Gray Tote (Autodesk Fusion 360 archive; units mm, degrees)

design "Gray Tote" references "Air Volume Tank", "Pnuematic Hub", "Assorted terminals 3", "assorted terminals 2", "Neo 550 Motor", "assorted terminals 1", "Battery", "CIM Motor", "Robot Radio", "Power Distribution Hub", "NI roboRIO", "Spark Max Motor Controller", "Compressor VIAIR"
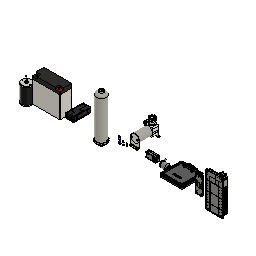
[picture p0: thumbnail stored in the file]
component_insert "Component Insert1"
component_insert "Component Insert4"
component_insert "Component Insert7"
component_insert "Component Insert8"
component_insert "Component Insert9"
component_insert "Component Insert10"
component_insert "Component Insert13"
component_insert "Component Insert15"
component_insert "Component Insert16"
component_insert "Component Insert17"
component_insert "Component Insert18"
component_insert "Component Insert19"
component_insert "Component Insert20"

design "Compressor VIAIR"
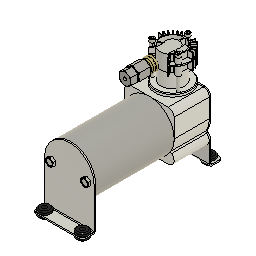
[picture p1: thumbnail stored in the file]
base_feature "Base Feature1"
base_feature "Base Feature1"
base_feature "Base Feature1"
base_feature "Base Feature1"
base_feature "Base Feature1"
base_feature "Base Feature1"
base_feature "Base Feature1"
base_feature "Base Feature1"
base_feature "Base Feature1"
base_feature "Base Feature1"
base_feature "Base Feature1"
as_built_joint "As-built1"
joint "Assemble1" alignAngle -180 alignOffsetX 0 alignOffsetY 0 alignOffsetZ 0
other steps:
create_component "CreateComponent1"
create_component "CreateComponent2"
create_component "CreateComponent3"
create_component "CreateComponent4"
create_component "CreateComponent5"
create_component "CreateComponent6"
create_component "CreateComponent7"
create_component "CreateComponent8"
create_component "CreateComponent9"
create_component "CreateComponent10"
create_component "CreateComponent11"
joint_origin "JointOrigin2"
joint_origin "JointOrigin2"

design "Battery"
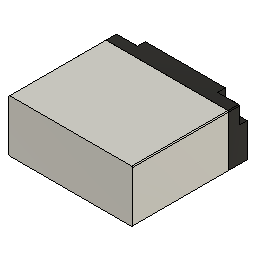
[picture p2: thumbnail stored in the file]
description: Robot Battery
part number: Robot Battery
base_feature "Base Feature"

design "CIM Motor"
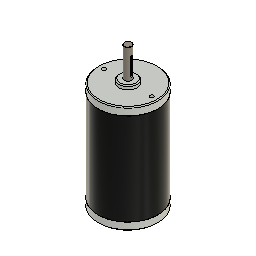
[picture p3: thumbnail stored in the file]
base_feature "Base Feature"

design "Robot Radio"
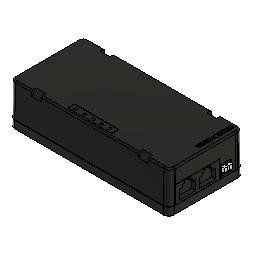
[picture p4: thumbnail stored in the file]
description: STEP AP214
part number: VH-109 Public 2024-01-02
base_feature "Base Feature"

design "Air Volume Tank"
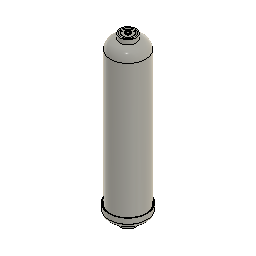
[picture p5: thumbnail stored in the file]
base_feature "Base Feature1"
base_feature "Base Feature1"
base_feature "Base Feature1"
base_feature "Base Feature1"
as_built_joint "As-built1"
joint "Assemble1" alignAngle 0 alignOffsetX 0 alignOffsetY 0 alignOffsetZ 0
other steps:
create_component "CreateComponent1"
create_component "CreateComponent2"
create_component "CreateComponent3"
create_component "CreateComponent4"
joint_origin "JointOrigin1"
joint_origin "JointOrigin1"

design "Neo 550 Motor"
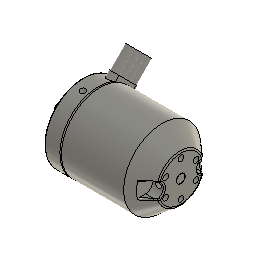
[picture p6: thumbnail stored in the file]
base_feature "Base Feature"

design "Pnuematic Hub"
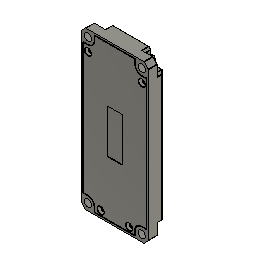
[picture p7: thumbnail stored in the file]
base_feature "Base Feature" bodies "Terminals (4)", "RS485 (1)", "RS485", "USB C", "Pin Connector", "Switch", "Terminals (2)", "Terminals (3)"
named bodies: "Terminals (4)", "RS485 (1)", "RS485", "USB C", "Pin Connector", "Switch", "Terminals (2)", "Terminals (3)", "Terminals", "Terminals (1)", "Outer Housing", "Bottom Housing", "Top Plate", "Screw", "Screw (1)", "Screw (2)", "Screw (3)"

design "NI roboRIO"
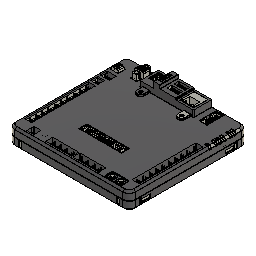
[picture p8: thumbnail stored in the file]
base_feature "Base Feature"

design "Assorted terminals 3"
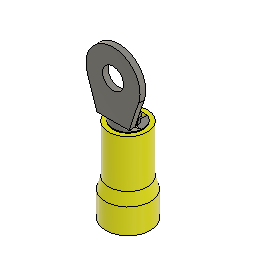
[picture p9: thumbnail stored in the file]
base_feature "Base Feature"

design "assorted terminals 2"
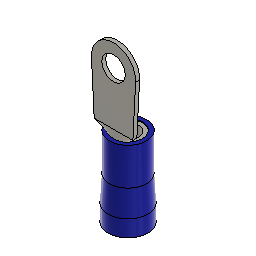
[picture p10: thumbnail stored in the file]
base_feature "Base Feature"

design "Power Distribution Hub"
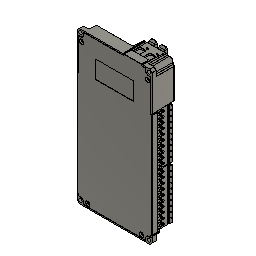
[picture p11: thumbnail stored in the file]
base_feature "Base Feature" bodies "Top Housing", "Bottom Housing", "Readout", "Screw (3)", "Screw (2)", "Screw (1)", "Screw", "Terminals (6)"
named bodies: "Top Housing", "Bottom Housing", "Readout", "Screw (3)", "Screw (2)", "Screw (1)", "Screw", "Terminals (6)", "USB C", "3 Pin (1)", "3 Pin", "Terminals (5)", "Terminals (4)", "Terminals (3)", "Terminals (2)", "Terminals (1)", "Terminals"

design "Spark Max Motor Controller"
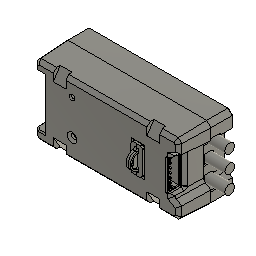
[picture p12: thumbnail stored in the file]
base_feature "Base Feature"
